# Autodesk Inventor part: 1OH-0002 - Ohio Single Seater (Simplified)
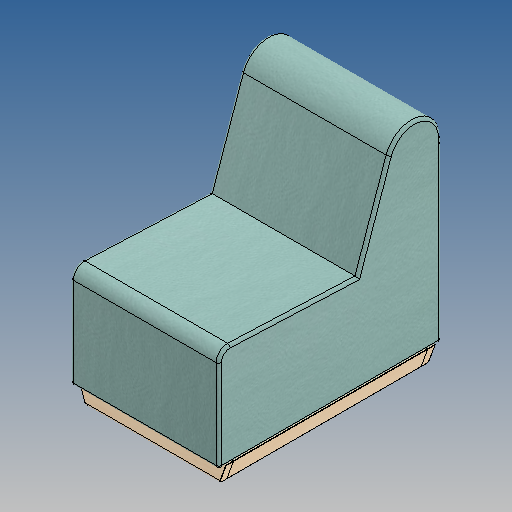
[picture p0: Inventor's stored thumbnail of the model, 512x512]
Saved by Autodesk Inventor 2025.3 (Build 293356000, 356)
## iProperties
Created: 2025-11
Part Number: 1OH-0002 - Ohio Single Seater (Simplified)
Material: Generic
Document SubType Name: Modeling
Designer: craig.ferris
Density: 1 g/cm^3
Appearance: CADET-ZEST SEAFOAM (219)
Author: craig.ferris
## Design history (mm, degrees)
derived "1OH-0002 - Ohio Single Seater with Upholstery (Rev C).iam"
body "Solid1"
body "Solid2"
body "Solid3"
body "Solid4"
body "Solid5"
body "Solid6"
body "Solid7"
body "Solid8"
body "Solid9"
body "Solid10"
